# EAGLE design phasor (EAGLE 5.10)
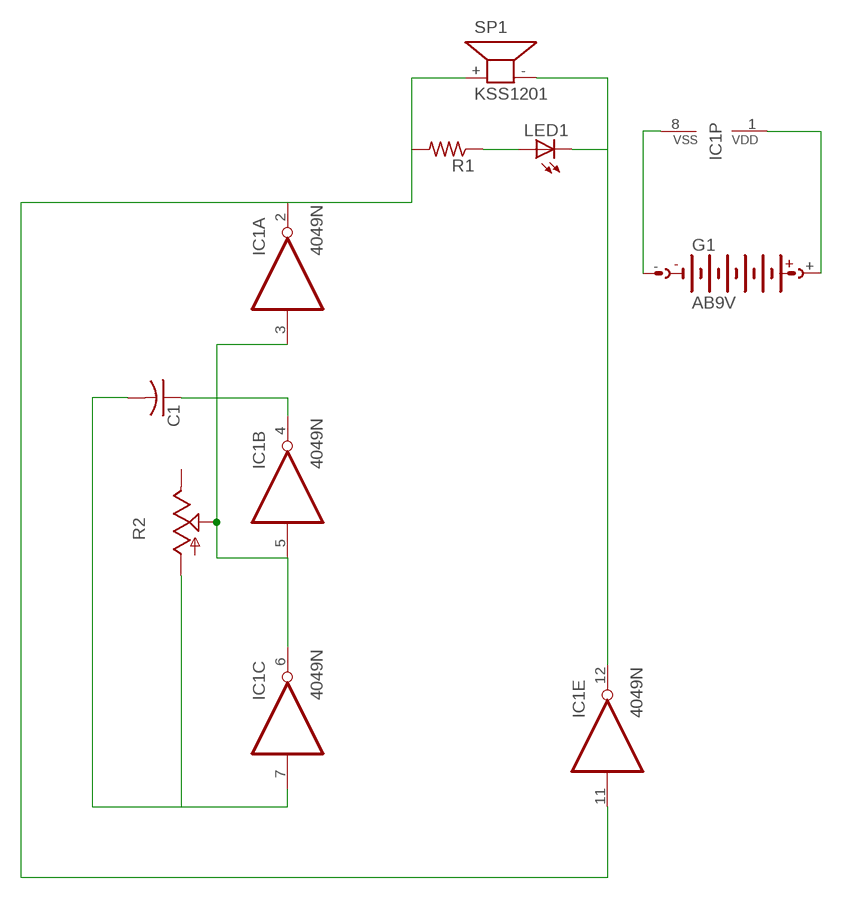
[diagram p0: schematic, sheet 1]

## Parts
C1  C-US025-040X050  [C025-040X050]
G1  AB9V  [AB9V]
IC1  4049N  [DIL16]
LED1  LED5MM  [LED5MM]
R1  R-US_V234/12  [V234/12]
R2  TRIM_US-S64W  [S64W]
SP1  KSS1201  [KSS1201]

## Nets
N$1: IC1.2(A:O) IC1.11(E:I) R1.2 SP1.+
N$2: LED1.A R1.1
N$3: IC1.12(E:O) LED1.K(C) SP1.-
N$4: C1.1 IC1.4(B:O)
N$5: C1.2 IC1.7(C:I) R2.A
N$6: IC1.3(A:I) IC1.5(B:I) IC1.6(C:O) R2.S
N$7: G1.- IC1.8(P:VSS)
N$8: G1.+ IC1.1(P:VDD)
Unconnected: IC1.9(D:I) IC1.10(D:O) IC1.14(F:I) IC1.15(F:O) R2.E

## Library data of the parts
C1 = resistor:C-US: CAPACITOR, American symbol
G1 = battery:AB9V: 9-V BATTERY CLIP
IC1 = 40xx:4049: Hex inverting BUFFER
LED1 = led:LED: LED
R1 = resistor:R-US_: RESISTOR, American symbol
R2 = pot:TRIM_US-: POTENTIOMETER
SP1 = buzzer:KSS1201: SPEAKER

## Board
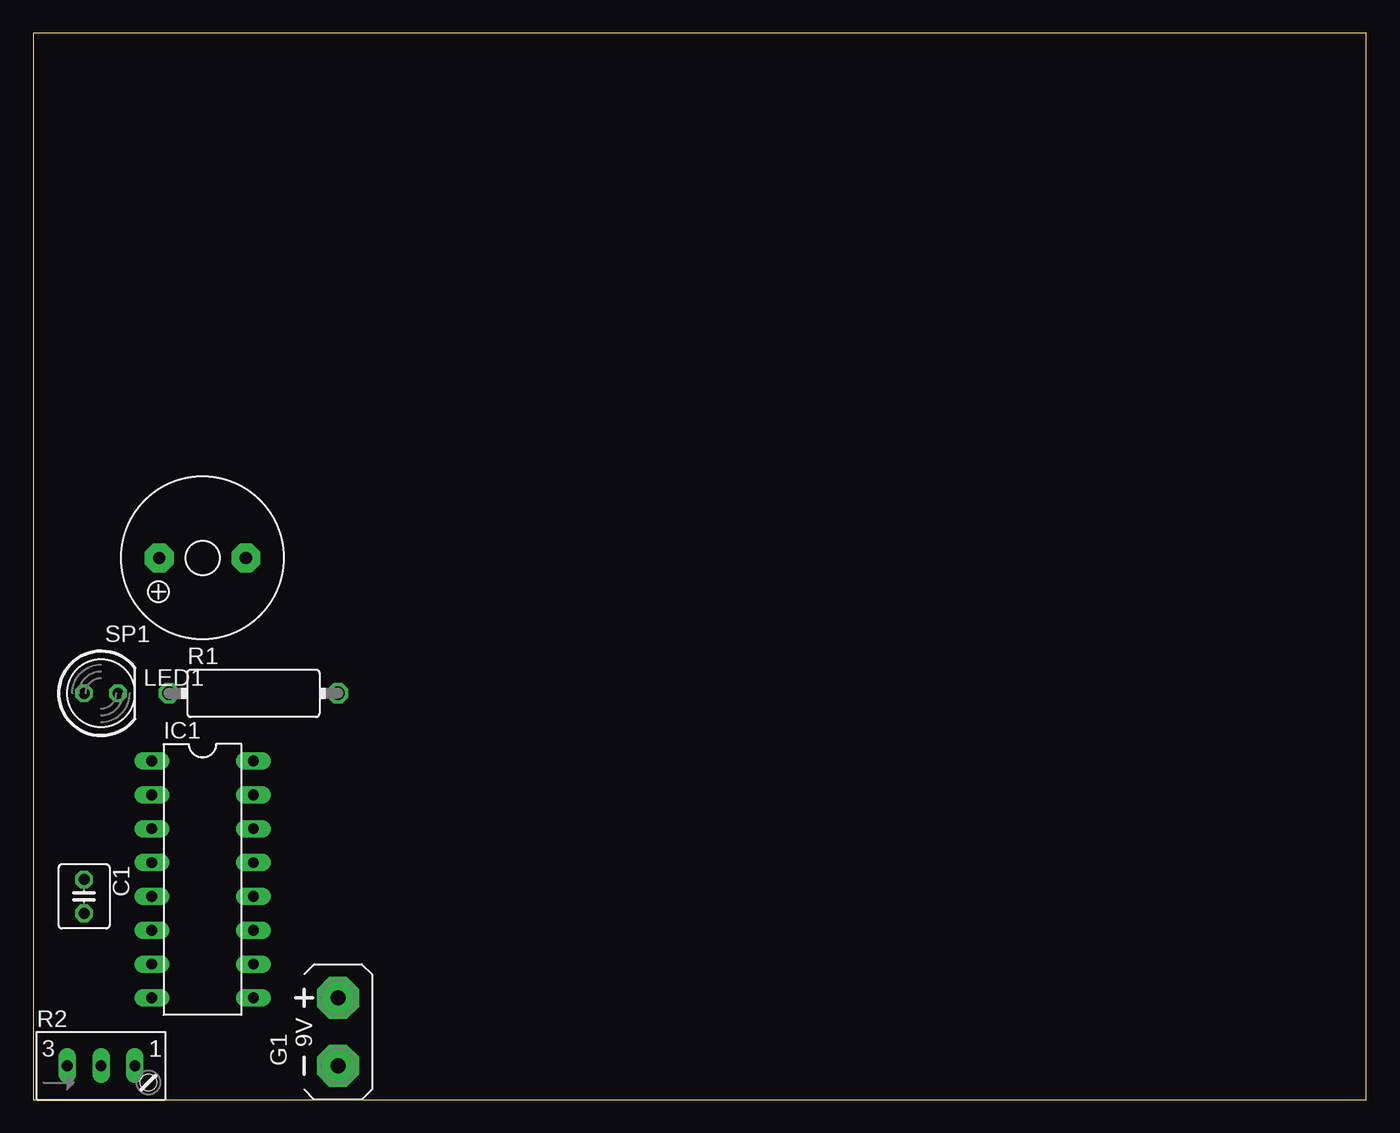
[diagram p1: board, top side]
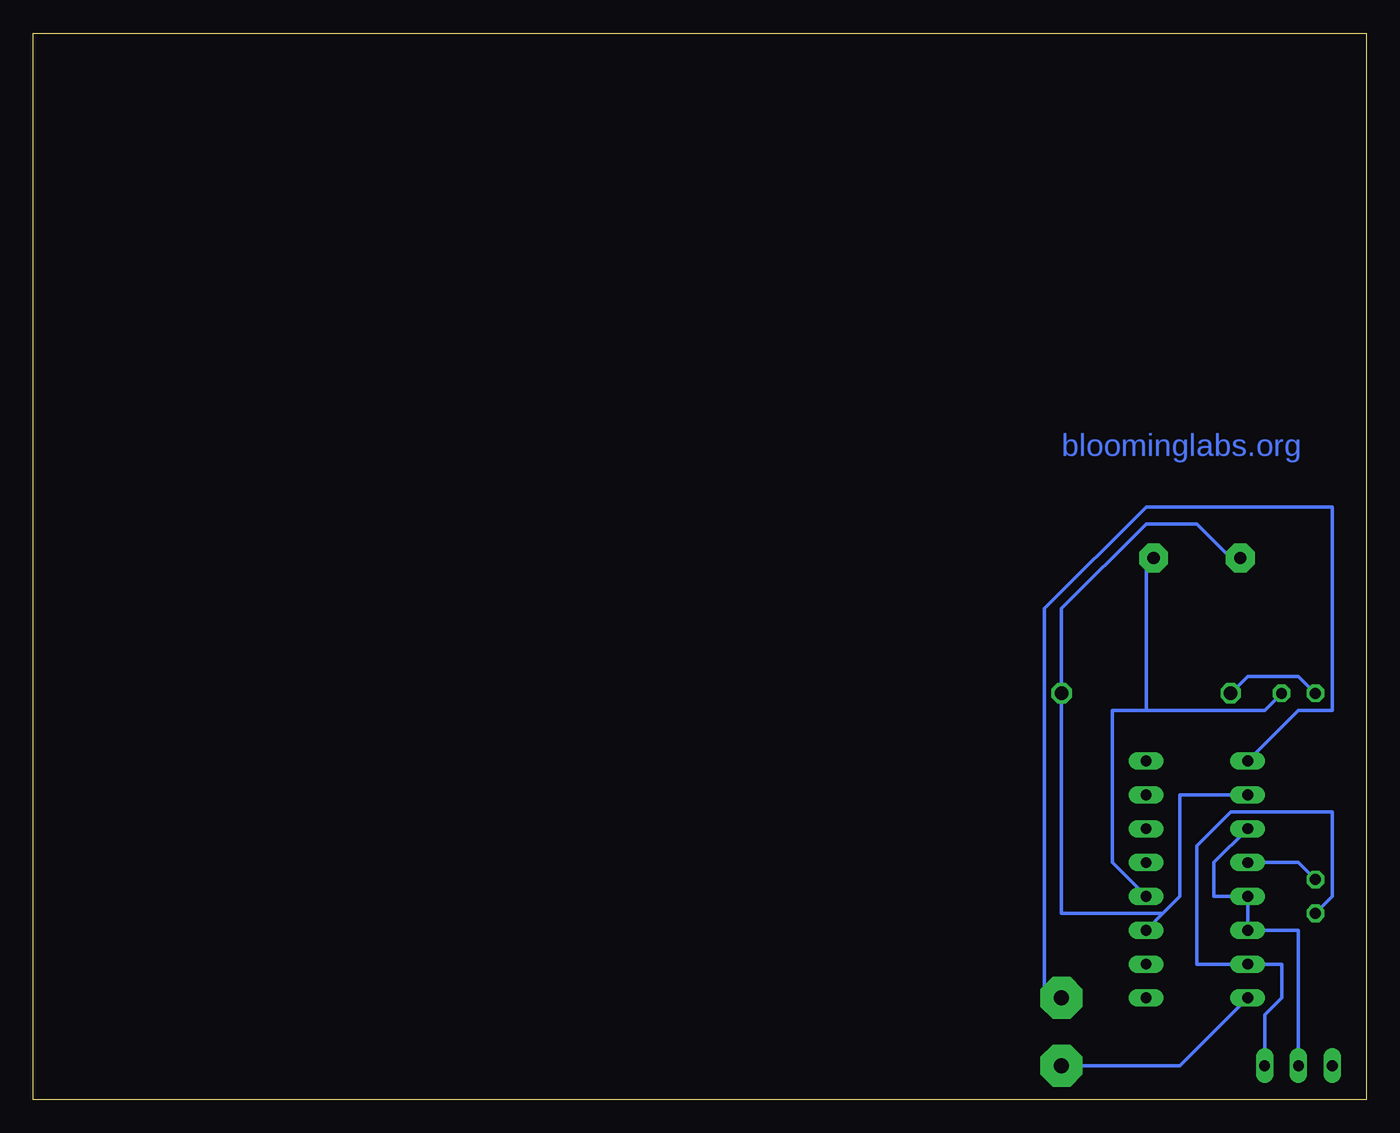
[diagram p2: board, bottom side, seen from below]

Size 100 x 80 mm. Coordinates in mm from the lower left corner, seen from the top.
Outline: 0,0 100,0 100,80 0,80 0,0
Copper layers (1*16): Top 0.035mm / dielectric 1.5mm / Bottom 0.035mm
Design rules "default": minimum track width 10mil, minimum drill 24mil, track to track 8mil, track to pad 8mil, pad to pad 8mil, via to via 8mil, smd to smd 8mil, copper to edge 40mil, drill to drill 8mil, minimum pad ring 10mil, minimum via ring 8mil, stop-mask expansion 4mil, vias tented up to drill 0mil, thermal gap 10mil

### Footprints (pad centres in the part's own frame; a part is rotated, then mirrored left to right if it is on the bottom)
C025-040X050 = drill 0.813 octagon: 1 -1.27,0; 2 1.27,0
AB9V = drill 1.118 pad 3.15 octagon: + 0,2.54; - 0,-2.54
DIL16 = drill 0.813 long: 1 -8.89,-3.81; 2 -6.35,-3.81; 3 -3.81,-3.81; 4 -1.27,-3.81; 5 1.27,-3.81; 6 3.81,-3.81; 7 6.35,-3.81; 8 8.89,-3.81; 9 8.89,3.81; 10 6.35,3.81; 11 3.81,3.81; 12 1.27,3.81; 13 -1.27,3.81; 14 -3.81,3.81; 15 -6.35,3.81; 16 -8.89,3.81
LED5MM = drill 0.813 octagon: A -1.27,0; K 1.27,0
V234/12 = drill 1.016 octagon: 1 -6.35,0; 2 6.35,0
S64W = drill 0.813 long: A 2.54,1.27; E -2.54,1.27; S 0,1.27
KSS1201 = drill 0.914 pad 2.159 octagon: + 3.251,0; - -3.251,0

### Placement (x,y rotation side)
C1  3.81,15.24 270 top
G1  22.86,5.08 0 top
IC1  12.7,16.51 270 top
LED1  5.08,30.48 0 top
R1  16.51,30.48 0 top
R2  5.08,1.27 0 top
SP1  12.7,40.64 180 top

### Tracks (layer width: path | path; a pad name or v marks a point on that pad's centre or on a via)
N$1
  Bottom 0.254: 15.24,13.97 13.97,15.24 13.97,22.86 IC1.2 | IC1.11 15.24,13.97 | 15.24,13.97 22.86,13.97 R1.2 22.86,36.83 16.51,43.18 12.7,43.18 10.16,40.64 SP1.+
N$2
  Bottom 0.254: LED1.A 5.08,31.75 8.89,31.75 R1.1
N$3
  Bottom 0.254: IC1.12 19.05,17.78 19.05,29.21 16.51,29.21 | 16.51,29.21 7.62,29.21 LED1.K | 16.51,29.21 16.51,40.64 SP1.-
N$4
  Bottom 0.254: C1.1 5.08,17.78 IC1.4
N$5
  Bottom 0.254: R2.A 7.62,6.35 6.35,7.62 6.35,10.16 IC1.7 12.7,10.16 12.7,19.05 10.16,21.59 2.54,21.59 2.54,15.24 C1.2
N$6
  Bottom 0.254: R2.S 5.08,12.7 IC1.6 IC1.5 11.43,15.24 11.43,17.78 IC1.3
N$7
  Bottom 0.254: IC1.8 13.97,2.54 G1.-
N$8
  Bottom 0.254: IC1.1 5.08,29.21 2.54,29.21 2.54,44.45 16.51,44.45 24.13,36.83 24.13,7.62 G1.+

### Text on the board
Bottom: bloominglabs.org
